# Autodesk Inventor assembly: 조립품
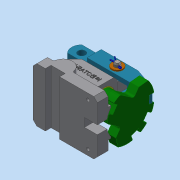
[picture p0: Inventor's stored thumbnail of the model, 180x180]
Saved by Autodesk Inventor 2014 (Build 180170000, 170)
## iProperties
Created: 2022-08
Part Number: 조립품
Document SubType Name: Assembly
Designer: dg
Author: dg
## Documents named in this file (8)
- C:\Users\dg\Desktop\720806V1005\조립품.iam
- C:\Users\dg\Desktop\720806V1005\본체.ipt
- C:\Users\dg\Desktop\720806V1005\분할축.ipt
- C:\Users\dg\Desktop\720806V1005\부시.ipt
- C:\Users\dg\Desktop\720806V1005\분할대.ipt
- C:\Users\dg\Desktop\720806V1005\와셔.ipt
- C:\Users\dg\Desktop\720806V1005\클레비스핀.ipt
- C:\Users\dg\Desktop\720806V1005\분할핀.ipt
